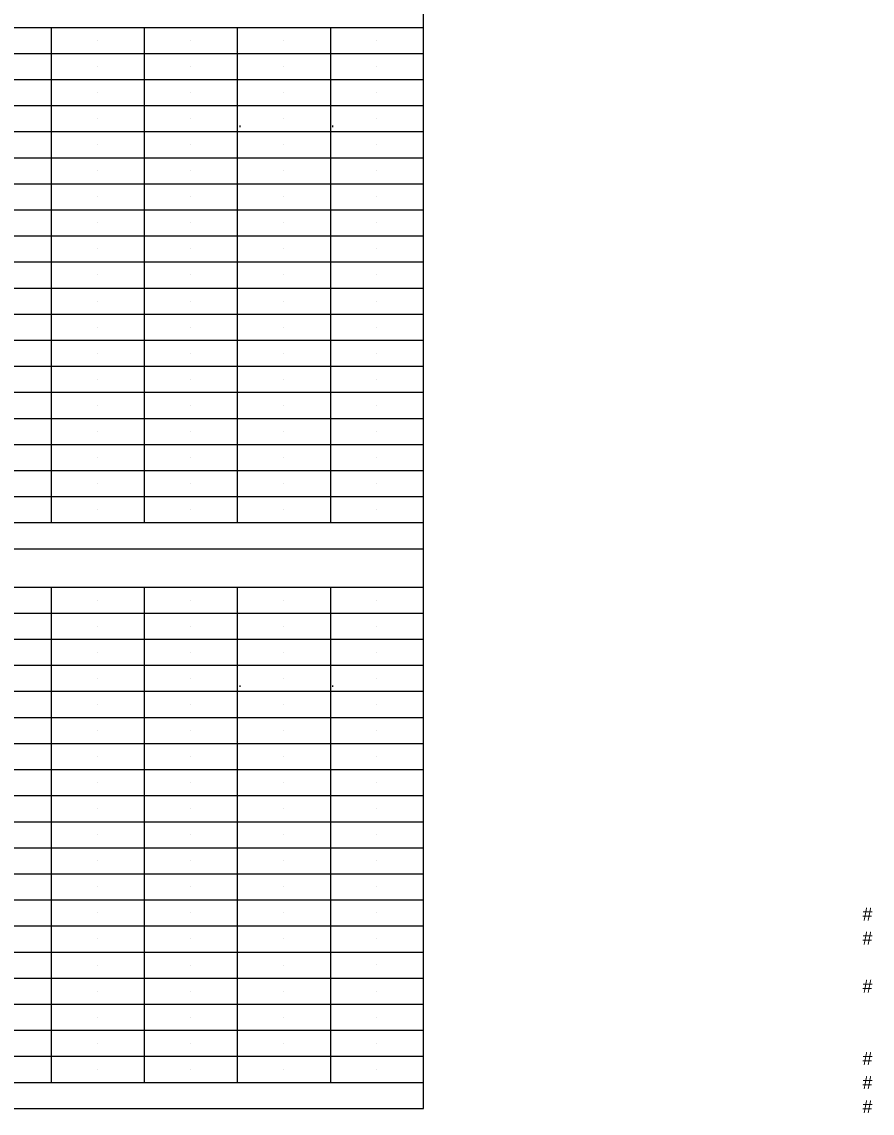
# Model space of a CAD drawing. Extents: x -16.6 to 33.3, y -8.6 to 39.2.
# Drawn here: x -7.32 to 1.82, y 1.23 to 12.95 of the extents above; entities that cross this region are included whole.
import ezdxf

# ---------------------------------------------------------------- set-up
doc = ezdxf.new("R2010")
doc.units = 0
doc.layers.add('BR_X_Beam_Centerline', color=7, linetype='Continuous')

msp = doc.modelspace()

# ---------------------------------------------------------------- linework, layer by layer
at = {"layer": 'BR_X_Beam_Centerline'}
for p, q in [((-3.003, 7.291), (-3.003, 20.715)), ((-16.637, 12.891), (-3.003, 12.891)), ((-7.003, 12.891), (-7.003, 7.571)), ((-6.003, 12.891), (-6.003, 7.571)), ((-5.003, 12.891), (-5.003, 7.571)), ((-4.003, 12.891), (-4.003, 7.571)), ((-4.003, 12.891), (-4.003, 7.571)), ((-6.503, 12.751), (-6.503, 12.751)), ((-5.503, 12.751), (-5.503, 12.751)), ((-4.503, 12.751), (-4.503, 12.751)), ((-3.503, 12.751), (-3.503, 12.751)), ((-16.637, 12.611), (-3.003, 12.611)), ((-6.503, 12.471), (-6.503, 12.471)), ((-5.503, 12.471), (-5.503, 12.471)), ((-4.503, 12.471), (-4.503, 12.471)), ((-3.503, 12.471), (-3.503, 12.471)), ((-16.637, 12.331), (-3.003, 12.331)), ((-6.503, 12.191), (-6.503, 12.191)), ((-5.503, 12.191), (-5.503, 12.191)), ((-4.503, 12.191), (-4.503, 12.191)), ((-3.503, 12.191), (-3.503, 12.191)), ((-16.637, 12.051), (-3.003, 12.051)), ((-6.503, 11.911), (-6.503, 11.911)), ((-5.503, 11.911), (-5.503, 11.911)), ((-4.503, 11.911), (-4.503, 11.911)), ((-3.503, 11.911), (-3.503, 11.911)), ((-16.637, 11.771), (-3.003, 11.771)), ((-4.973, 11.819), (-4.973, 11.835)), ((-3.978, 11.819), (-3.978, 11.835)), ((-6.503, 11.631), (-6.503, 11.631)), ((-5.503, 11.631), (-5.503, 11.631)), ((-4.503, 11.631), (-4.503, 11.631)), ((-3.503, 11.631), (-3.503, 11.631)), ((-16.637, 11.491), (-3.003, 11.491)), ((-6.503, 11.351), (-6.503, 11.351)), ((-5.503, 11.351), (-5.503, 11.351)), ((-4.503, 11.351), (-4.503, 11.351)), ((-3.503, 11.351), (-3.503, 11.351)), ((-16.637, 11.211), (-3.003, 11.211)), ((-6.503, 11.071), (-6.503, 11.071)), ((-5.503, 11.071), (-5.503, 11.071)), ((-4.503, 11.071), (-4.503, 11.071)), ((-3.503, 11.071), (-3.503, 11.071)), ((-16.637, 10.931), (-3.003, 10.931)), ((-6.503, 10.791), (-6.503, 10.791)), ((-5.503, 10.791), (-5.503, 10.791)), ((-4.503, 10.791), (-4.503, 10.791)), ((-3.503, 10.791), (-3.503, 10.791)), ((-16.637, 10.651), (-3.003, 10.651)), ((-6.503, 10.511), (-6.503, 10.511)), ((-5.503, 10.511), (-5.503, 10.511)), ((-4.503, 10.511), (-4.503, 10.511)), ((-3.503, 10.511), (-3.503, 10.511)), ((-16.637, 10.371), (-3.003, 10.371)), ((-6.503, 10.231), (-6.503, 10.231)), ((-5.503, 10.231), (-5.503, 10.231)), ((-4.503, 10.231), (-4.503, 10.231)), ((-3.503, 10.231), (-3.503, 10.231)), ((-16.637, 10.091), (-3.003, 10.091)), ((-6.503, 9.951), (-6.503, 9.951)), ((-5.503, 9.951), (-5.503, 9.951)), ((-4.503, 9.951), (-4.503, 9.951)), ((-3.503, 9.951), (-3.503, 9.951)), ((-16.637, 9.811), (-3.003, 9.811)), ((-6.503, 9.671), (-6.503, 9.671)), ((-5.503, 9.671), (-5.503, 9.671)), ((-4.503, 9.671), (-4.503, 9.671)), ((-3.503, 9.671), (-3.503, 9.671)), ((-16.637, 9.531), (-3.003, 9.531)), ((-6.503, 9.391), (-6.503, 9.391)), ((-5.503, 9.391), (-5.503, 9.391)), ((-4.503, 9.391), (-4.503, 9.391)), ((-3.503, 9.391), (-3.503, 9.391)), ((-16.637, 9.251), (-3.003, 9.251)), ((-6.503, 9.111), (-6.503, 9.111)), ((-5.503, 9.111), (-5.503, 9.111)), ((-4.503, 9.111), (-4.503, 9.111)), ((-3.503, 9.111), (-3.503, 9.111)), ((-16.637, 8.971), (-3.003, 8.971)), ((-6.503, 8.831), (-6.503, 8.831)), ((-5.503, 8.831), (-5.503, 8.831)), ((-4.503, 8.831), (-4.503, 8.831)), ((-3.503, 8.831), (-3.503, 8.831)), ((-16.637, 8.691), (-3.003, 8.691)), ((-6.503, 8.551), (-6.503, 8.551)), ((-5.503, 8.551), (-5.503, 8.551)), ((-4.503, 8.551), (-4.503, 8.551)), ((-3.503, 8.551), (-3.503, 8.551)), ((-16.637, 8.411), (-3.003, 8.411)), ((-6.503, 8.271), (-6.503, 8.271)), ((-5.503, 8.271), (-5.503, 8.271)), ((-4.503, 8.271), (-4.503, 8.271)), ((-3.503, 8.271), (-3.503, 8.271)), ((-16.637, 8.131), (-3.003, 8.131)), ((-6.503, 7.991), (-6.503, 7.991)), ((-5.503, 7.991), (-5.503, 7.991)), ((-4.503, 7.991), (-4.503, 7.991)), ((-3.503, 7.991), (-3.503, 7.991)), ((-16.637, 7.851), (-3.003, 7.851)), ((-6.503, 7.711), (-6.503, 7.711)), ((-5.503, 7.711), (-5.503, 7.711)), ((-4.503, 7.711), (-4.503, 7.711)), ((-3.503, 7.711), (-3.503, 7.711)), ((-16.637, 7.571), (-3.003, 7.571)), ((-16.637, 7.291), (-3.003, 7.291)), ((-3.003, 1.279), (-3.003, 7.291)), ((-16.637, 6.879), (-3.003, 6.879)), ((-7.003, 6.879), (-7.003, 1.559)), ((-6.003, 6.879), (-6.003, 1.559)), ((-5.003, 6.879), (-5.003, 1.559)), ((-4.003, 6.879), (-4.003, 1.559)), ((-4.003, 6.879), (-4.003, 1.559)), ((-6.503, 6.739), (-6.503, 6.739)), ((-5.503, 6.739), (-5.503, 6.739)), ((-4.503, 6.739), (-4.503, 6.739)), ((-3.503, 6.74), (-3.503, 6.74)), ((-16.637, 6.599), (-3.003, 6.599)), ((-6.503, 6.459), (-6.503, 6.459)), ((-5.503, 6.459), (-5.503, 6.459)), ((-4.503, 6.459), (-4.503, 6.459)), ((-3.503, 6.46), (-3.503, 6.46)), ((-16.637, 6.319), (-3.003, 6.319)), ((-6.503, 6.179), (-6.503, 6.179)), ((-5.503, 6.179), (-5.503, 6.179)), ((-4.503, 6.179), (-4.503, 6.179)), ((-3.503, 6.18), (-3.503, 6.18)), ((-16.637, 6.039), (-3.003, 6.039)), ((-6.503, 5.899), (-6.503, 5.899)), ((-5.503, 5.899), (-5.503, 5.899)), ((-4.503, 5.899), (-4.503, 5.899)), ((-3.503, 5.9), (-3.503, 5.9)), ((-16.637, 5.759), (-3.003, 5.759)), ((-4.973, 5.807), (-4.973, 5.823)), ((-3.978, 5.807), (-3.978, 5.823)), ((-6.503, 5.619), (-6.503, 5.619)), ((-5.503, 5.619), (-5.503, 5.619)), ((-4.503, 5.619), (-4.503, 5.619)), ((-3.503, 5.62), (-3.503, 5.62)), ((-16.637, 5.479), (-3.003, 5.479)), ((-6.503, 5.339), (-6.503, 5.339)), ((-5.503, 5.339), (-5.503, 5.339)), ((-4.503, 5.339), (-4.503, 5.339)), ((-3.503, 5.34), (-3.503, 5.34)), ((-16.637, 5.199), (-3.003, 5.199)), ((-6.503, 5.059), (-6.503, 5.059)), ((-5.503, 5.059), (-5.503, 5.059)), ((-4.503, 5.059), (-4.503, 5.059)), ((-3.503, 5.06), (-3.503, 5.06)), ((-16.637, 4.919), (-3.003, 4.919)), ((-6.503, 4.779), (-6.503, 4.779)), ((-5.503, 4.779), (-5.503, 4.779)), ((-4.503, 4.779), (-4.503, 4.779)), ((-3.503, 4.78), (-3.503, 4.78)), ((-16.637, 4.639), (-3.003, 4.639)), ((-6.503, 4.499), (-6.503, 4.499)), ((-5.503, 4.499), (-5.503, 4.499)), ((-4.503, 4.499), (-4.503, 4.499)), ((-3.503, 4.5), (-3.503, 4.5)), ((-16.637, 4.359), (-3.003, 4.359)), ((-6.503, 4.219), (-6.503, 4.219)), ((-5.503, 4.219), (-5.503, 4.219)), ((-4.503, 4.219), (-4.503, 4.219)), ((-3.503, 4.22), (-3.503, 4.22)), ((-16.637, 4.079), (-3.003, 4.079)), ((-6.503, 3.939), (-6.503, 3.939)), ((-5.503, 3.939), (-5.503, 3.939)), ((-4.503, 3.939), (-4.503, 3.939)), ((-3.503, 3.94), (-3.503, 3.94)), ((-16.637, 3.799), (-3.003, 3.799)), ((-6.503, 3.659), (-6.503, 3.659)), ((-5.503, 3.659), (-5.503, 3.659)), ((-4.503, 3.659), (-4.503, 3.659)), ((-3.503, 3.66), (-3.503, 3.66)), ((-16.637, 3.519), (-3.003, 3.519)), ((-6.503, 3.379), (-6.503, 3.379)), ((-5.503, 3.379), (-5.503, 3.379)), ((-4.503, 3.379), (-4.503, 3.379)), ((-3.503, 3.38), (-3.503, 3.38)), ((-16.637, 3.239), (-3.003, 3.239)), ((-6.503, 3.099), (-6.503, 3.099)), ((-5.503, 3.099), (-5.503, 3.099)), ((-4.503, 3.099), (-4.503, 3.099)), ((-3.503, 3.1), (-3.503, 3.1)), ((-16.637, 2.959), (-3.003, 2.959)), ((-6.503, 2.819), (-6.503, 2.819)), ((-5.503, 2.819), (-5.503, 2.819)), ((-4.503, 2.819), (-4.503, 2.819)), ((-3.503, 2.82), (-3.503, 2.82)), ((-16.637, 2.679), (-3.003, 2.679)), ((-6.503, 2.539), (-6.503, 2.539)), ((-5.503, 2.539), (-5.503, 2.539)), ((-4.503, 2.539), (-4.503, 2.539)), ((-3.503, 2.54), (-3.503, 2.54)), ((-16.637, 2.399), (-3.003, 2.399)), ((-6.503, 2.259), (-6.503, 2.259)), ((-5.503, 2.259), (-5.503, 2.259)), ((-4.503, 2.259), (-4.503, 2.259)), ((-3.503, 2.26), (-3.503, 2.26)), ((-16.637, 2.119), (-3.003, 2.119)), ((-6.503, 1.979), (-6.503, 1.979)), ((-5.503, 1.979), (-5.503, 1.979)), ((-4.503, 1.979), (-4.503, 1.979)), ((-3.503, 1.98), (-3.503, 1.98)), ((-16.637, 1.839), (-3.003, 1.839)), ((-6.503, 1.699), (-6.503, 1.699)), ((-5.503, 1.699), (-5.503, 1.699)), ((-4.503, 1.699), (-4.503, 1.699)), ((-3.503, 1.7), (-3.503, 1.7)), ((-16.637, 1.559), (-3.003, 1.559)), ((-16.637, 1.279), (-3.003, 1.279))]:
    msp.add_line(p, q, dxfattribs=at)

# ---------------------------------------------------------------- texts
for p in [(1.717, 3.297), (1.717, 3.039), (1.717, 2.521), (1.717, 1.745), (1.717, 1.487), (1.717, 1.228)]:
    msp.add_text('#', height=0.14, dxfattribs=at).set_placement(p)

doc.saveas('drawing.dxf')
